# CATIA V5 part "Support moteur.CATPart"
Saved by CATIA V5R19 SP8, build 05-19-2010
Part number: Support moteur
Nomenclature: 6_a
Material "Acier": density 7860 kg/m3, Young's modulus 2e+11 Pa, Poisson ratio 0.266, thermal expansion 1.17e-05 1/K
Bounding box of the stored display mesh (mm): x -50 to 50, y -79.927 to 103.048, z -29.499 to 3
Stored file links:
  C:\Users\rphgr\Desktop\0_Tapis_TC520B_vitesse\Support moteur.CATPart
  D:\Documents\1_Travail\1 - ac-limoges.fr\ac-limoges.fr\Emmanuel Maynard - STI2D_Turgot\3 - Supports\Tapis de course TC520B\Tapis de course TC520B_Ca\0_Tapis_TC520B.CATProduct
  D:\Documents\1_Travail\1 - ac-limoges.fr\ac-limoges.fr\Emmanuel Maynard - STI2D_Turgot\3 - Supports\Tapis de course TC520B\Tapis de course TC520B_Ca\Cadre Plateau.CATPart
  D:\Programmes\DassaultSysteme\win_b64\startup\materials\French\Catalog.CATMaterial
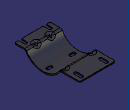
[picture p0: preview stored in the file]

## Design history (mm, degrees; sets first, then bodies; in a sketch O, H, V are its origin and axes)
SheetMetalParameters1: Thickness 3, BendRadius 4, KFactor 0.356492 {= log(min(100,max(20*SheetMetalParameters1.BendRadius,SheetMetalParameters1.Thickness)/SheetMetalParameters1.Thickness))/log(100)/2}, ReliefRadialLength 1, ReliefAxialLength 2, MinimumBendRadius 0
AxisSystem1: origin (0, 0, 0), X (1, 0, 0), Y (0, 1, 0), Z (0, 0, 1)
Set1
  DatumSurface1
  DatumSurface2
Body1 (main body), material "Acier"
  Sketch1 on YZ plane of AxisSystem1, origin (0, 0, 0), H (0, 1, 0), V (0, 0, 1)
    line L1 (-79.9274, 0) -> (-49.9274, 0)
    point P1 (-79.9274, 0)
    line L2 (48.1534, -3) -> (103.048, -3)
    point P2 (103.048, -3)
    arc A1 centre (0, 27.5) radius 57 from (-49.9274, 0) to (48.1534, -3) ccw
    point P3 (0, 27.5)
    reference intersected line E1 (179, -3) -> (216, -3) from face of DatumSurface2
    reference projected line E2 through (0, 0) direction (0, 1) from edge [ZX plane of AxisSystem1 | YZ plane of AxisSystem1]
    radius A1 = 57
    distance A1 L2 = 26.5
    length L1 = 30
    distance P2 P1 = 183
    distance L1 L2 = 3
    horizontal: L1 H, L2 H
    coincidence: L2 E1, E2 P3
  d_Extrusion1: Extrude_Thickness 3, KFacteur 0.356492 {= log(min(100,max(20*SheetMetalParameters1.BendRadius,SheetMetalParameters1.Thickness)/SheetMetalParameters1.Thickness))/log(100)/2}, Extrude_Profile Sketch1, Extrude_StartLength 50, Extrude_EndLength 50, Extrude_Radius 4, Extrude_DeductionTable SheetMetalParameters1, Extrude_FixedPoint Sketch1.P1
  Sketch2 on , origin (1.7858, -47.2233, 2.5729), H (1, 0, 0), V (0, 0.939, -0.344)
    point P1 (18.2142, 0)
    reference intersected line E1 through (48.2142, 0) direction (0, 1) from face of d_Extrusion1
    distance P1 E1 = 30
  d_Stamp1: NewRoot_AttribNormalisation "No Standard", Stamp_FilletRadius 11
  Sketch3 on , origin (-25.3079, -46.9819, 2.4793), H (1, 0, 0), V (0, 0.9256, -0.3785)
    point P1 (5.3079, 0)
    reference intersected line E1 through (-24.6921, 0) direction (0, -1) from face of d_Extrusion1
    distance P1 E1 = 30
  d_Stamp2: NewRoot_AttribNormalisation "No Standard", Stamp_FilletRadius 11
  Sketch4 on , origin (-32.0291, 45.0453, -0.5985), H (1, 0, 0), V (0, 0.9145, 0.4046)
    point P1 (-5.9709, 0)
    reference intersected line E1 (-17.9709, -65.8769) -> (-17.9709, -61.0697) from face of d_Extrusion1
    distance P1 E1 = 12
  d_Stamp3: NewRoot_AttribNormalisation "No Standard", Stamp_FilletRadius 11
  Sketch5 on , origin (34.3206, 46.1269, -0.2224), H (1, 0, 0), V (0, 0.9682, 0.2501)
    point P1 (3.6794, 0)
    reference intersected line E1 through (15.6794, 0) direction (0, -1) from face of d_Extrusion1
    distance P1 E1 = 12
  d_Stamp4: NewRoot_AttribNormalisation "No Standard", Stamp_FilletRadius 11
  Corner1: CornerChamferEdges (edge [face of d_Extrusion1 | face of d_Extrusion1]; edge [face of d_Extrusion1 | face of d_Extrusion1]; edge [face of d_Extrusion1 | face of d_Extrusion1]; edge [face of d_Extrusion1 | face of d_Extrusion1]), CornerRadius 4
  Sketch6 on face of d_Extrusion1, origin (0, 0, -3), H (1, 0, 0), V (0, -1, 0)
    construction line L1 (35, -77.048) -> (35, -93.048)
    point P2 (35, -93.048)
    line L2 (39.5, -77.048) -> (39.5, -93.048)
    line L3 (30.5, -93.048) -> (30.5, -77.048)
    arc A1 centre (35, -93.048) radius 4.5 from (39.5, -93.048) to (30.5, -93.048) cw
    arc A2 centre (35, -77.048) radius 4.5 from (30.5, -77.048) to (39.5, -77.048) cw
    construction line L4 (-35, -77.048) -> (-35, -93.048)
    point P8 (-35, -93.048)
    line L5 (-30.5, -77.048) -> (-30.5, -93.048)
    line L6 (-39.5, -93.048) -> (-39.5, -77.048)
    arc A3 centre (-35, -93.048) radius 4.5 from (-30.5, -93.048) to (-39.5, -93.048) cw
    arc A4 centre (-35, -77.048) radius 4.5 from (-39.5, -77.048) to (-30.5, -77.048) cw
    reference intersected line E1 (-50, -105.7817) -> (-50, -47.8774) from face of d_Extrusion1
    reference intersected line E2 (50, -103.048) -> (-50, -103.048) from face of d_Extrusion1
    reference intersected line E3 (50, -103.048) -> (-50, -103.048) from face of d_Extrusion1
    distance L1 L2 = 4.5
    distance L4 L5 = 4.5
    length L4 = 16
    length L1 = 16
    distance L4 L1 = 70
    distance L4 E1 = 15
    distance P8 E2 = 10
    distance P2 E3 = 10
    vertical: L1 V, L4 V
    tangency: A1 L2, A2 L2, A1 L3, A2 L3, A3 L5, A4 L5, A3 L6, A4 L6
  CutOut1: Direction Sketch6, EndLimit length 3, Orientation true, Profile Sketch6, StartLimit length 0
  Sketch7 on face of d_Extrusion1, origin (0, 0, 0), H (1, 0, 0), V (0, -1, 0)
    construction line L1 (35, 64.9274) -> (35, 79.9274)
    point P1 (35, 64.9274)
    point P2 (35, 79.9274)
    line L2 (30.5, 64.9274) -> (30.5, 79.9274)
    line L3 (39.5, 79.9274) -> (39.5, 64.9274)
    arc A1 centre (35, 79.9274) radius 4.5 from (30.5, 79.9274) to (39.5, 79.9274) cw
    arc A2 centre (35, 64.9274) radius 4.5 from (39.5, 64.9274) to (30.5, 64.9274) cw
    construction line L4 (-35, 64.9274) -> (-35, 79.9274)
    point P7 (-35, 64.9274)
    point P8 (-35, 79.9274)
    line L5 (-39.5, 64.9274) -> (-39.5, 79.9274)
    line L6 (-30.5, 79.9274) -> (-30.5, 64.9274)
    arc A3 centre (-35, 79.9274) radius 4.5 from (-39.5, 79.9274) to (-30.5, 79.9274) cw
    arc A4 centre (-35, 64.9274) radius 4.5 from (-30.5, 64.9274) to (-39.5, 64.9274) cw
    reference intersected line E1 (-50, 79.9274) -> (50, 79.9274) from face of d_Extrusion1
    reference intersected line E2 (-50, 79.9274) -> (50, 79.9274) from face of d_Extrusion1
    reference intersected line E3 (-50, 79.9274) -> (50, 79.9274) from face of d_Extrusion1
    reference intersected line E4 (-50, 79.9274) -> (50, 79.9274) from face of d_Extrusion1
    reference projected point E5 (35, -77.048) from axis of face of CutOut1
    reference projected point E6 (-35, -77.048) from axis of face of CutOut1
    distance L1 L2 = 4.5
    distance L4 L5 = 4.5
    distance P1 E3 = 15
    distance P7 E4 = 15
    vertical: L1 V, L4 V
    tangency: A1 L2, A2 L2, A1 L3, A2 L3, A3 L5, A4 L5, A3 L6, A4 L6
    coincidence: P8 E1, P2 E2, L1 E5, L4 E6
  CutOut2: Direction Sketch7, EndLimit length 3, Orientation true, Profile Sketch7, StartLimit length 0
  Sketch8 on XY plane of AxisSystem1, origin (0, 0, 0), H (1, 0, 0), V (0, 1, 0)
    construction line L1 (-36.5, 0) -> (-28.5, 0)
    point P1 (-36.5, 0)
    point P2 (-28.5, 0)
    line L2 (-36.5, 4.5) -> (-28.5, 4.5)
    line L3 (-28.5, -4.5) -> (-36.5, -4.5)
    arc A1 centre (-28.5, 0) radius 4.5 from (-28.5, 4.5) to (-28.5, -4.5) cw
    arc A2 centre (-36.5, 0) radius 4.5 from (-36.5, -4.5) to (-36.5, 4.5) cw
    construction line L4 (28.5, 0) -> (36.5, 0)
    point P7 (28.5, 0)
    line L5 (28.5, 4.5) -> (36.5, 4.5)
    line L6 (36.5, -4.5) -> (28.5, -4.5)
    arc A3 centre (36.5, 0) radius 4.5 from (36.5, 4.5) to (36.5, -4.5) cw
    arc A4 centre (28.5, 0) radius 4.5 from (28.5, -4.5) to (28.5, 4.5) cw
    reference intersected line E1 through (0, 0) direction (0, 1) from YZ plane of AxisSystem1
    distance L1 L2 = 4.5
    distance L4 L5 = 4.5
    length L1 = 8
    length L4 = 8
    distance P7 P2 = 57
    distance P7 E1 = 28.5
    coincidence: P1 H, P7 H
    horizontal: L1 H, L4 H
    tangency: A1 L2, A2 L2, A1 L3, A2 L3, A3 L5, A4 L5, A3 L6, A4 L6
  CutOut3: Direction Sketch8, EndLimit length 36, Orientation true, Profile Sketch8, StartLimit length 0.01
